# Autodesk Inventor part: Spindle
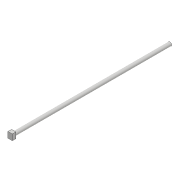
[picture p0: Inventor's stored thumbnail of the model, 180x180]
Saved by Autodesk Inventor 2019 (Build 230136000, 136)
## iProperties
Created: 2018-04
Part Number: Spindle
Material: 一般
Document SubType Name: Modeling
Designer: ADJ
Density: 1 g/cm^3
Appearance: 既定
Mass: 4461.52 g
Surface Area: 3613.21 cm^2
Volume: 4461.52 cm^3
Author: ADJ
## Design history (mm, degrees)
derived "gate_skelton.ipt"
  sketch "スケッチ1"
    geometry: L1 (-600, 0)-(600, 0) reference; L2 (600, 0)-(600, 800) reference; L3 (600, 800)-(-600, 800) reference; L4 (-600, 800)-(-600, 0) reference; L5 (-550, 633.333)-(550, 633.333) reference; L6 (550, 533.333)-(-550, 533.333) reference; L7 (-550, 266.667)-(550, 266.667) reference; L8 (550, 166.667)-(-550, 166.667) reference; L9 (-50, 800)-(-50, 0) reference; L10 (50, 800)-(50, 0) reference; L11 (0, 0)-(0, 800) reference; L12 (-550, 750)-(550, 750) reference; L13 (550, 750)-(550, 50) reference; L14 (550, 50)-(-550, 50) reference; L15 (-550, 50)-(-550, 750) reference; L16 (-700, 0)-(700, 0) reference; L17 (700, 0)-(700, 2000) reference; L18 (700, 2000)-(-700, 2000) reference; L19 (-700, 2000)-(-700, 0) reference; L20 (0, 800)-(0, 3000) reference; 5 further points
sketch "スケッチ2"
  geometry: L1 (0, 3000)-(25, 3000); L2 (25, 3000)-(25, 800); L3 (25, 800)-(0, 800); L4 (0, 800)-(0, 3000); L5 (0, 800)-(0, 3000) reference; L6 (600, 800)-(-600, 800) reference; 1 further point
  constraints: 8 end point, 2 collinear, 2 parallel, 1 horizontal, 1 perpendicular
  dimensions: "d1" = 25 distance of L1.start L1.end
revolve "回転1" sketch "スケッチ2" stored, may be unused: angle "d2" = 90 deg
sketch "スケッチ3"
  geometry: L1 (-30, -40)-(30, -40); L2 (30, -40)-(30, 40); L3 (30, 40)-(-30, 40); L4 (-30, 40)-(-30, -40); L5 (-30, -40)-(30, 40); L6 (30, -40)-(-30, 40); C1 r 25 at (0, 0) reference
  constraints: 12 end point, 2 midpoint, 2 parallel, 1 horizontal, 1 perpendicular
  dimensions: "d3" = 60 distance of L1.start L1.end; "d4" = 80 distance of L1.end L2.end
extrude "押し出し1" join sketch "スケッチ3" distance "d5" = 50; taper "d6" = 0 deg
node "ソリッド1"
